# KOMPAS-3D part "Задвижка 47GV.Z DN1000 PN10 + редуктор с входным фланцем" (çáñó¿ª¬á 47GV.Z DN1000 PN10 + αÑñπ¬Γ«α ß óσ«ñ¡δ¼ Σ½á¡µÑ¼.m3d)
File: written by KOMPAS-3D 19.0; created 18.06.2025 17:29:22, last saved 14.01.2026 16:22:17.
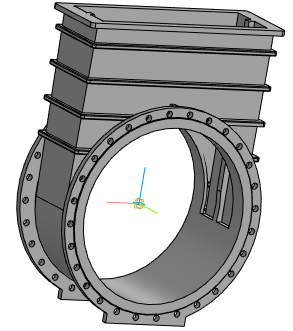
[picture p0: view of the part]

Document properties: Полное имя файла: Задвижка 47GV.Z DN1000 PN10 + редуктор с входным валом.a3d

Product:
- Part/product: Задвижка 47GV.Z DN1000 PN10 + редуктор с входным фланцем
    Масса: 4499.14
  - Body: Тело 1
      Масса: 1001.97

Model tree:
1. Операция без истории:1
2. Эскиз:1  (with: Операция без истории:1)
3. Элемент выдавливания:1
     Расстояние 2 = 1091
4. Эскиз:2  (with: Элемент выдавливания:1)
5. Элемент выдавливания:2
     Расстояние 2 = 1138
